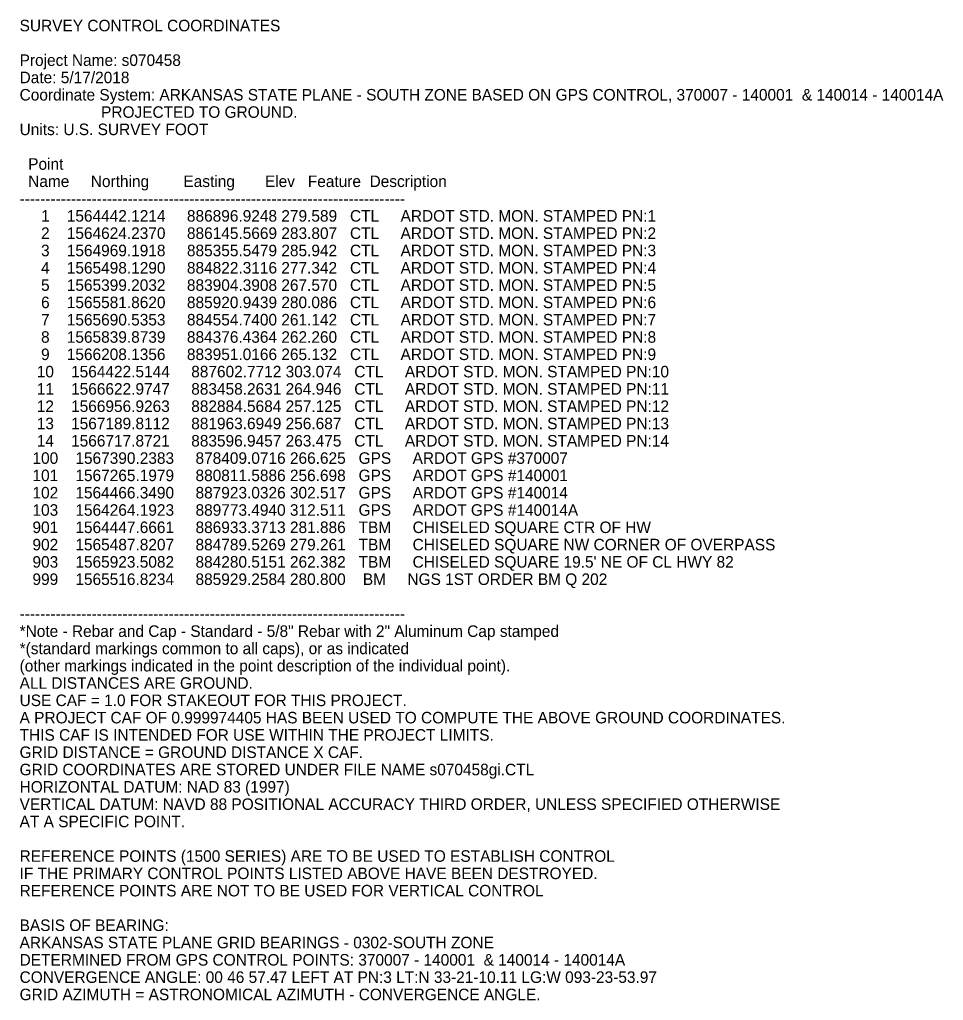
# Model space of a CAD drawing. Extents: x 878399 to 890772, y 1564242 to 1571231.
# Drawn here: x 888099 to 890772, y 1568392 to 1571231 of the extents above; entities that cross this region are included whole.
import ezdxf

# ---------------------------------------------------------------- set-up
doc = ezdxf.new("R2010")
doc.units = 0
doc.layers.add('Default', color=7, linetype='Continuous')

msp = doc.modelspace()

# ---------------------------------------------------------------- texts
at = {"layer": 'Default'}
for s, height, p in [('SURVEY CONTROL COORDINATES ', 33.398, (888099.3, 1571197.5)), ('Project Name: s070458 ', 33.398, (888099.3, 1571097.3)), ('Date: 5/17/2018 ', 33.398, (888099.3, 1571047.2)), ('Coordinate System: ARKANSAS STATE PLANE - SOUTH ZONE BASED ON GPS CONTROL, 370007 - 140001  & 140014 - 140014A', 33.3977, (888099.3, 1570997.1)), ('                   PROJECTED TO GROUND. ', 33.398, (888099.3, 1570947)), ('Units: U.S. SURVEY FOOT ', 33.398, (888099.3, 1570896.9)), ('  Point ', 33.4, (888099.3, 1570796.7)), ('  Name     Northing        Easting       Elev   Feature  Description ', 33.398, (888099.3, 1570746.6)), ('--------------------------------------------------------------------------- ', 33.398, (888099.3, 1570696.5)), ('     1    1564442.1214     886896.9248 279.589   CTL     ARDOT STD. MON. STAMPED PN:1 ', 33.398, (888099.3, 1570646.4)), ('     2    1564624.2370     886145.5669 283.807   CTL     ARDOT STD. MON. STAMPED PN:2 ', 33.398, (888099.3, 1570596.3)), ('     3    1564969.1918     885355.5479 285.942   CTL     ARDOT STD. MON. STAMPED PN:3 ', 33.398, (888099.3, 1570546.2)), ('     4    1565498.1290     884822.3116 277.342   CTL     ARDOT STD. MON. STAMPED PN:4 ', 33.398, (888099.3, 1570496.1)), ('     5    1565399.2032     883904.3908 267.570   CTL     ARDOT STD. MON. STAMPED PN:5 ', 33.398, (888099.3, 1570446)), ('     6    1565581.8620     885920.9439 280.086   CTL     ARDOT STD. MON. STAMPED PN:6 ', 33.398, (888099.3, 1570395.9)), ('     7    1565690.5353     884554.7400 261.142   CTL     ARDOT STD. MON. STAMPED PN:7 ', 33.398, (888099.3, 1570345.8)), ('     8    1565839.8739     884376.4364 262.260   CTL     ARDOT STD. MON. STAMPED PN:8 ', 33.398, (888099.3, 1570295.7)), ('     9    1566208.1356     883951.0166 265.132   CTL     ARDOT STD. MON. STAMPED PN:9 ', 33.398, (888099.3, 1570245.6)), ('    10    1564422.5144     887602.7712 303.074   CTL     ARDOT STD. MON. STAMPED PN:10 ', 33.398, (888099.3, 1570195.5)), ('    11    1566622.9747     883458.2631 264.946   CTL     ARDOT STD. MON. STAMPED PN:11 ', 33.398, (888099.3, 1570145.4)), ('    12    1566956.9263     882884.5684 257.125   CTL     ARDOT STD. MON. STAMPED PN:12 ', 33.398, (888099.3, 1570095.3)), ('    13    1567189.8112     881963.6949 256.687   CTL     ARDOT STD. MON. STAMPED PN:13 ', 33.398, (888099.3, 1570045.3)), ('    14    1566717.8721     883596.9457 263.475   CTL     ARDOT STD. MON. STAMPED PN:14 ', 33.398, (888099.3, 1569995.2)), ('   100    1567390.2383     878409.0716 266.625   GPS     ARDOT GPS #370007 ', 33.398, (888099.3, 1569945.1)), ('   101    1567265.1979     880811.5886 256.698   GPS     ARDOT GPS #140001 ', 33.398, (888099.3, 1569895)), ('   102    1564466.3490     887923.0326 302.517   GPS     ARDOT GPS #140014 ', 33.398, (888099.3, 1569844.9)), ('   103    1564264.1923     889773.4940 312.511   GPS     ARDOT GPS #140014A ', 33.398, (888099.3, 1569794.8)), ('   901    1564447.6661     886933.3713 281.886   TBM     CHISELED SQUARE CTR OF HW', 33.398, (888099.3, 1569744.7)), ('   902    1565487.8207     884789.5269 279.261   TBM     CHISELED SQUARE NW CORNER OF OVERPASS ', 33.398, (888099.3, 1569694.6)), ("   903    1565923.5082     884280.5151 262.382   TBM     CHISELED SQUARE 19.5' NE OF CL HWY 82 ", 33.398, (888099.3, 1569644.5)), ('   999    1565516.8234     885929.2584 280.800    BM     NGS 1ST ORDER BM Q 202 ', 33.398, (888099.3, 1569594.4)), ('--------------------------------------------------------------------------- ', 33.398, (888099.3, 1569494.2)), ('*Note - Rebar and Cap - Standard - 5/8" Rebar with 2" Aluminum Cap stamped ', 33.398, (888099.3, 1569444.1)), ('*(standard markings common to all caps), or as indicated ', 33.398, (888099.3, 1569394)), ('(other markings indicated in the point description of the individual point).  ', 33.398, (888099.3, 1569343.9)), ('ALL DISTANCES ARE GROUND. ', 33.398, (888099.3, 1569293.8)), ('USE CAF = 1.0 FOR STAKEOUT FOR THIS PROJECT. ', 33.398, (888099.3, 1569243.7)), ('A PROJECT CAF OF 0.999974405 HAS BEEN USED TO COMPUTE THE ABOVE GROUND COORDINATES. ', 33.398, (888099.3, 1569193.6)), ('THIS CAF IS INTENDED FOR USE WITHIN THE PROJECT LIMITS. ', 33.398, (888099.3, 1569143.5)), ('GRID DISTANCE = GROUND DISTANCE X CAF. ', 33.398, (888099.3, 1569093.4)), ('GRID COORDINATES ARE STORED UNDER FILE NAME s070458gi.CTL  ', 33.398, (888099.3, 1569043.3)), ('HORIZONTAL DATUM: NAD 83 (1997) ', 33.398, (888099.3, 1568993.2)), ('VERTICAL DATUM: NAVD 88 POSITIONAL ACCURACY THIRD ORDER, UNLESS SPECIFIED OTHERWISE  ', 33.398, (888099.3, 1568943.1)), ('AT A SPECIFIC POINT. ', 33.398, (888099.3, 1568893)), ('REFERENCE POINTS (1500 SERIES) ARE TO BE USED TO ESTABLISH CONTROL ', 33.398, (888099.3, 1568792.8)), ('IF THE PRIMARY CONTROL POINTS LISTED ABOVE HAVE BEEN DESTROYED. ', 33.398, (888099.3, 1568742.7)), ('REFERENCE POINTS ARE NOT TO BE USED FOR VERTICAL CONTROL ', 33.398, (888099.3, 1568692.6)), ('BASIS OF BEARING: ', 33.398, (888099.3, 1568592.5)), ('ARKANSAS STATE PLANE GRID BEARINGS - 0302-SOUTH ZONE ', 33.398, (888099.3, 1568542.4)), ('DETERMINED FROM GPS CONTROL POINTS: 370007 - 140001  & 140014 - 140014A', 33.398, (888099.3, 1568492.3)), ('CONVERGENCE ANGLE: 00 46 57.47 LEFT AT PN:3 LT:N 33-21-10.11 LG:W 093-23-53.97', 33.398, (888099.3, 1568442.2)), ('GRID AZIMUTH = ASTRONOMICAL AZIMUTH - CONVERGENCE ANGLE.', 33.398, (888099.3, 1568392.1))]:
    msp.add_text(s, height=height, dxfattribs=at).set_placement(p)

doc.saveas('drawing.dxf')
